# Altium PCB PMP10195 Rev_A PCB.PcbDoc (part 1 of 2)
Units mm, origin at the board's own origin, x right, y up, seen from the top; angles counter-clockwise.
Board outline 60.32 x 50 mm, 4 copper layers (Top Layer, Signal Layer 1, Signal Layer 2, Bottom Layer), stack 2.028 mm thick; 90 components, 50 nets, 184 pads, 78 vias.
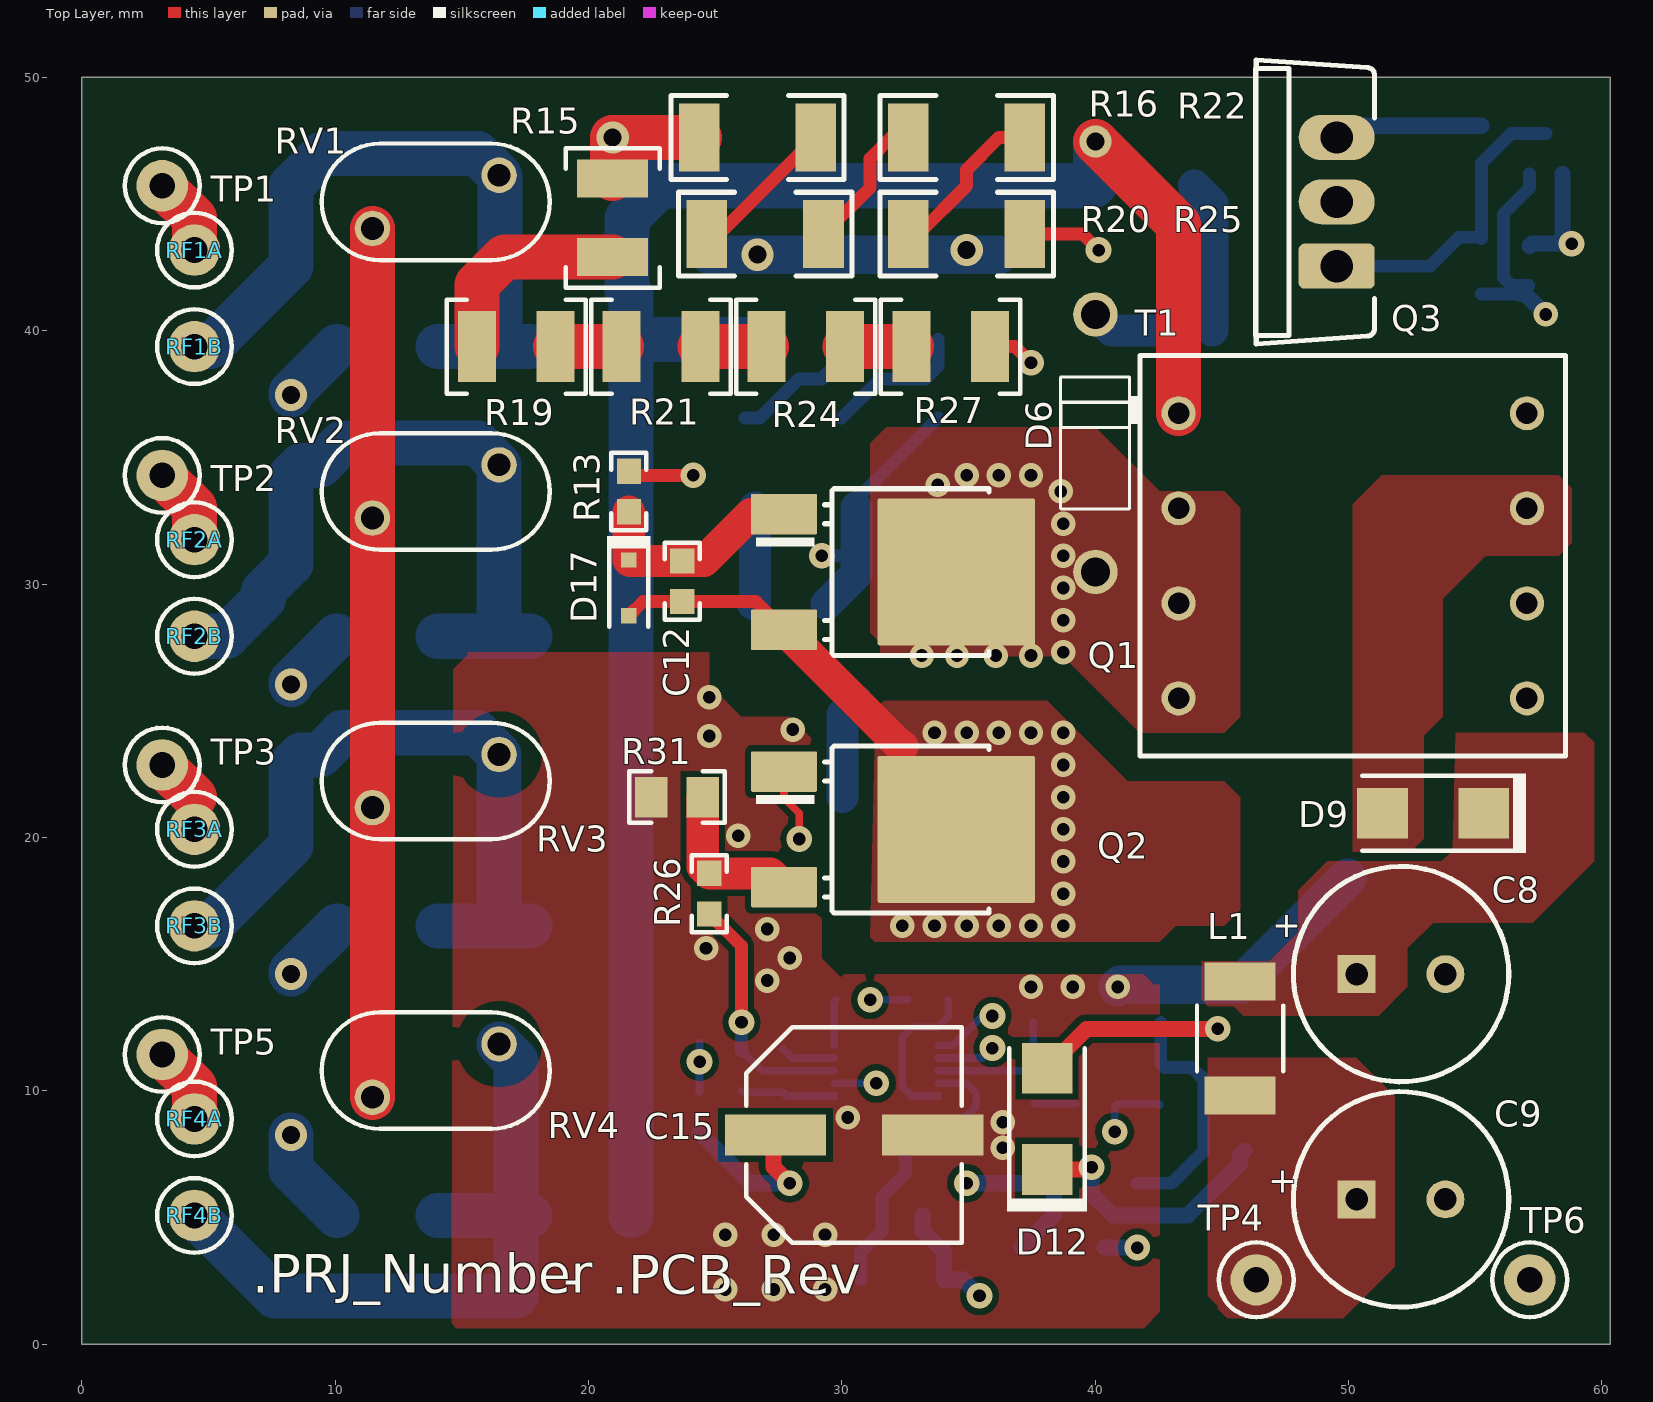
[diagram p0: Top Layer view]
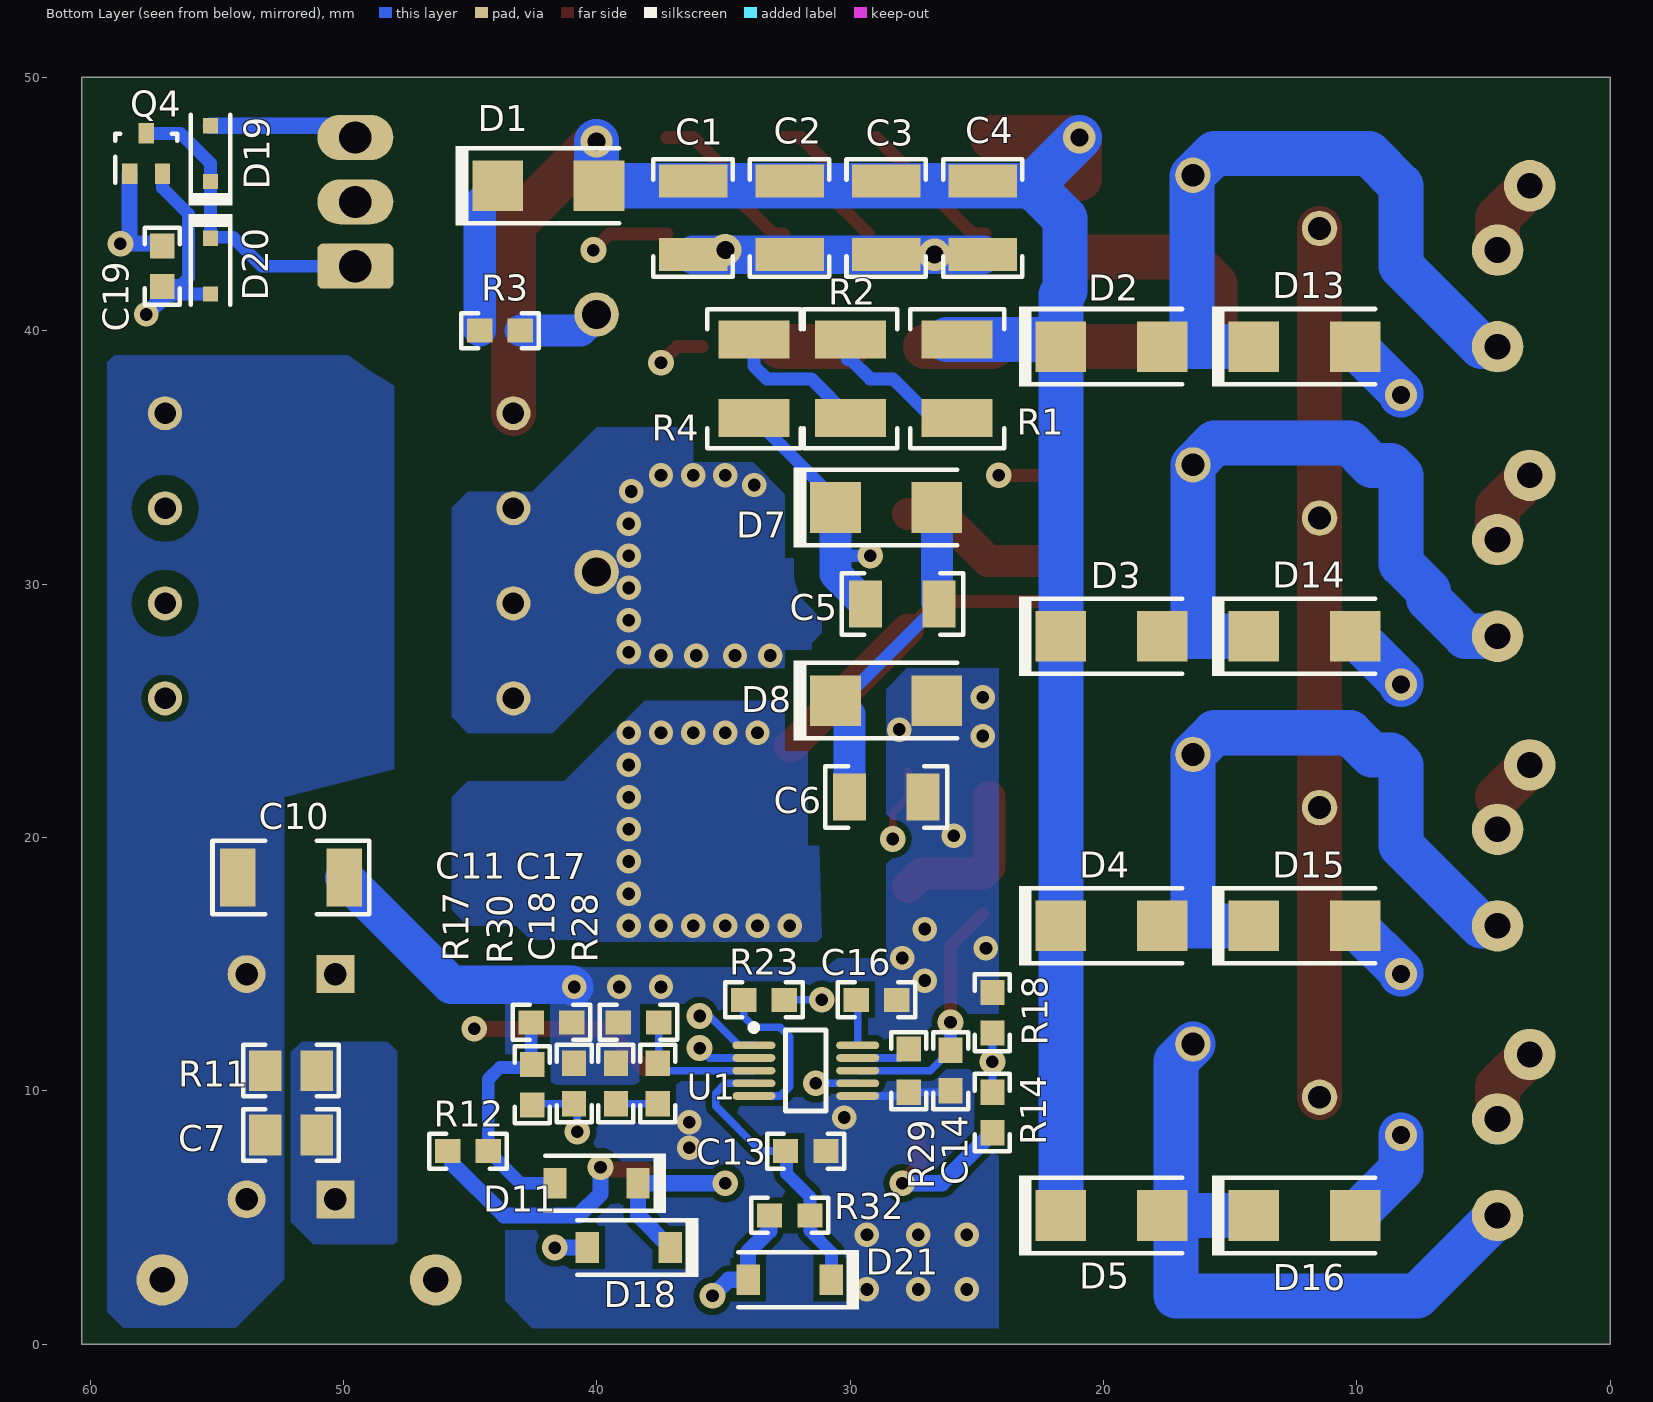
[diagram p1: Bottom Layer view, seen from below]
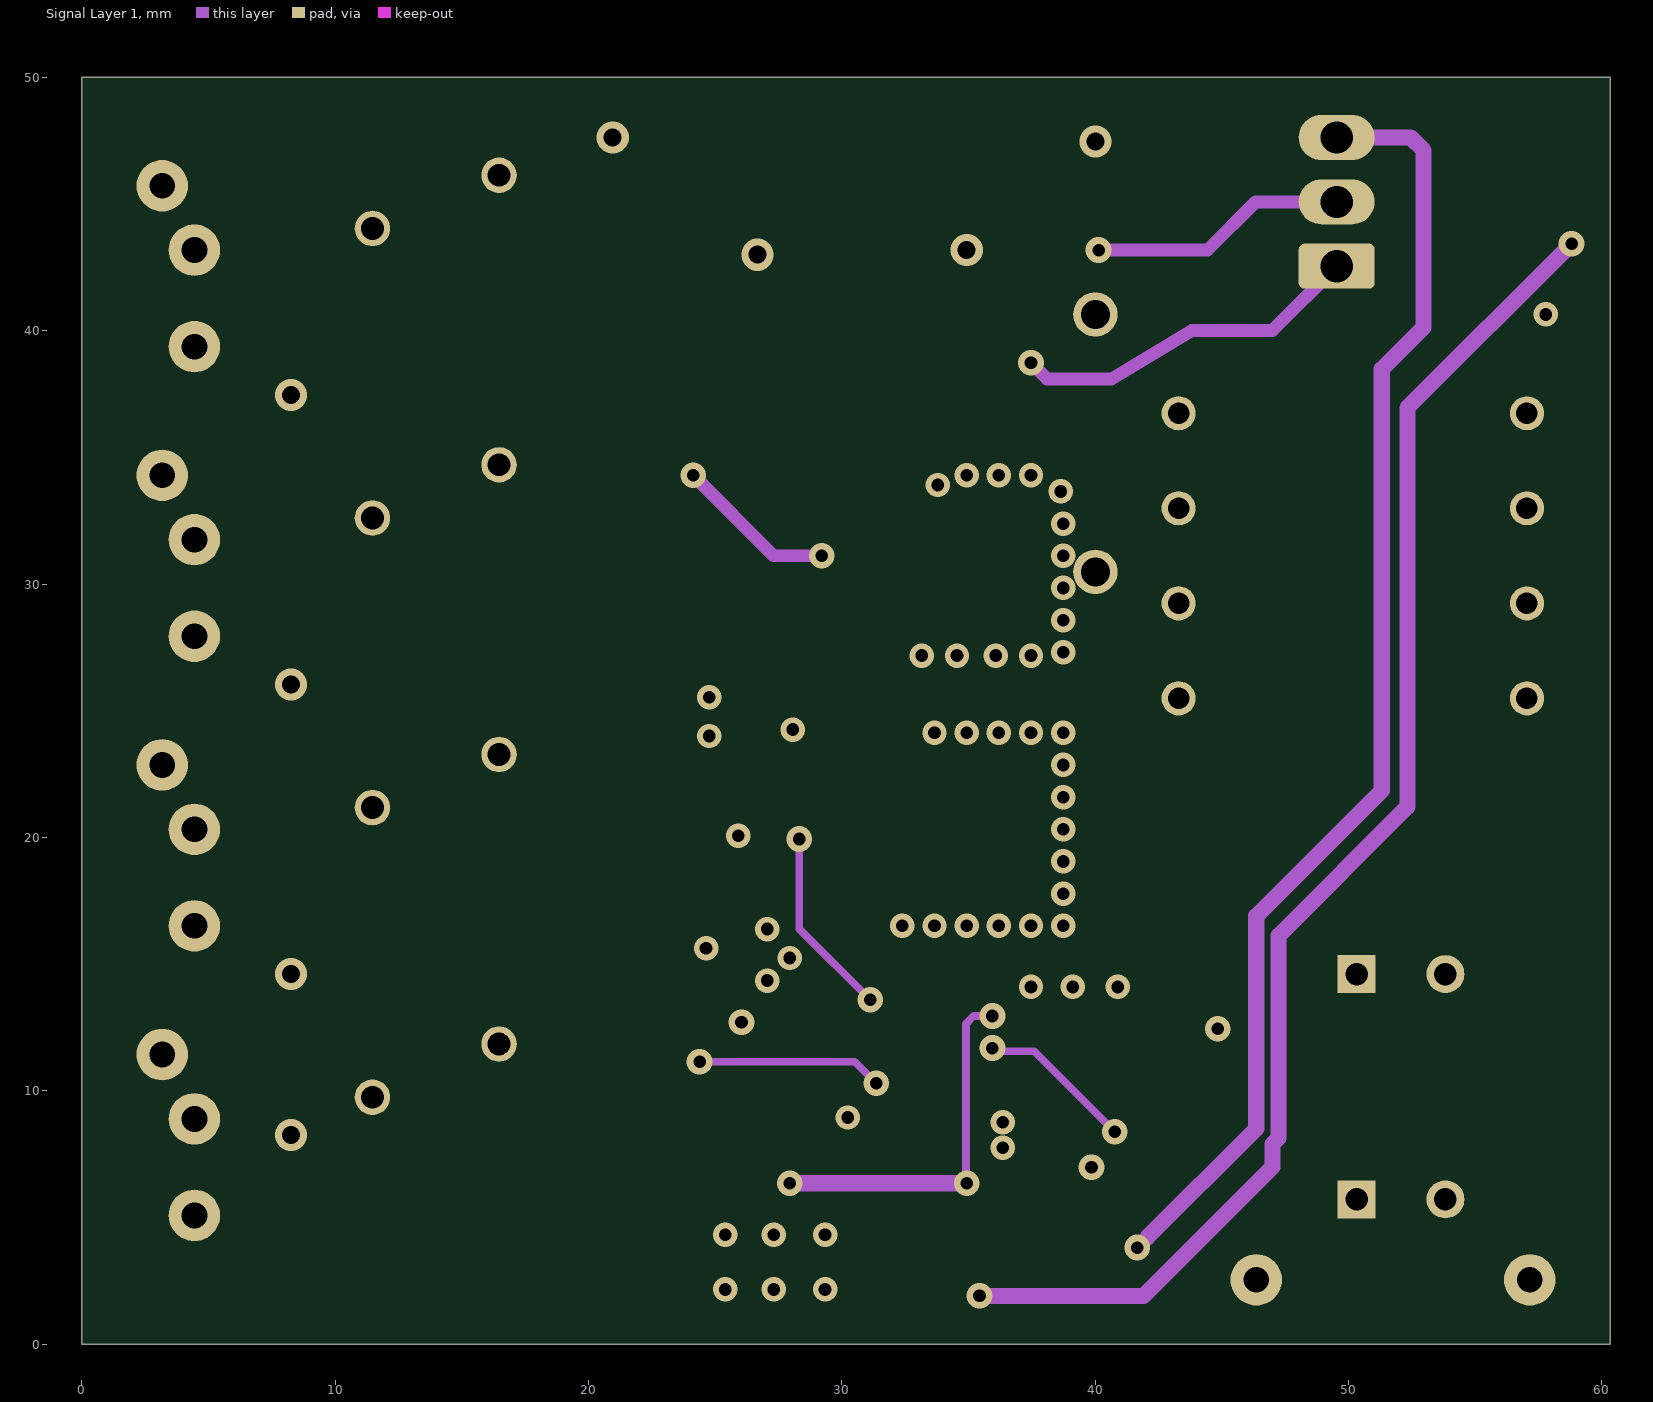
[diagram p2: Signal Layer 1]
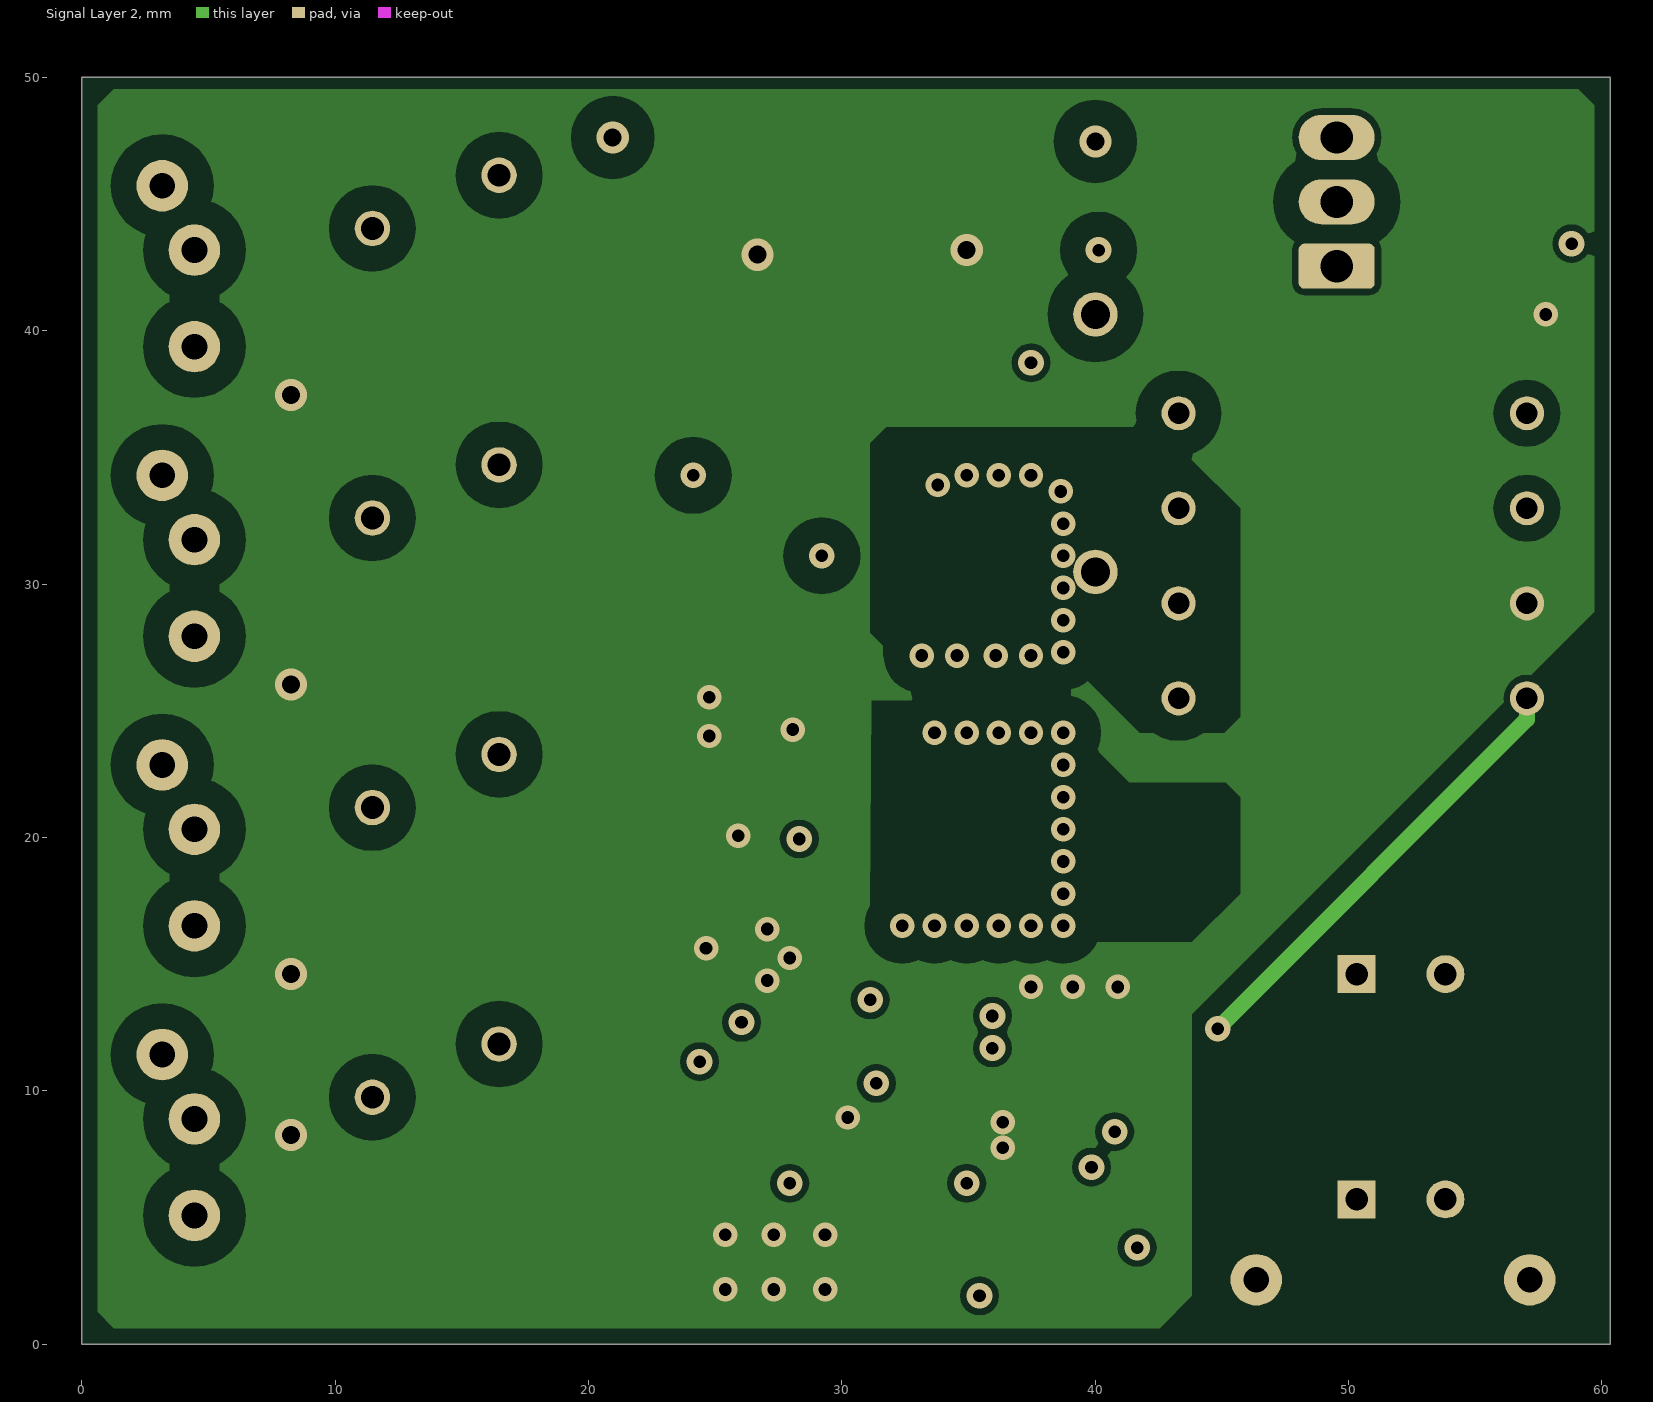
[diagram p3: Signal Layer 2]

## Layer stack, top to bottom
Top Solder: solder mask 0.0102, Solder Resist, Dk 3.5
Top Layer: signal copper 0.0356
Dielectric1: core 1.5037, FR-4, Dk 4.8
Signal Layer 1: signal copper 0.036
Dielectric 2: prepreg 0.127, Dk 4.2
Signal Layer 2: signal copper 0.036
Dielectric 3: core 0.254, Dk 4.2
Bottom Layer: signal copper 0.0356
Bottom Solder: solder mask 0.0102, Solder Resist, Dk 3.5

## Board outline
0,0 0,50 60.325,50 60.325,0

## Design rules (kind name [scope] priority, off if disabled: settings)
AcuteAngle [All] p1: minimum=4.50000000000000E+0001 checktracksonly=FALSE
AssemblyTestPointUsage [All] p1: valid=2
Clearance "Schematic Clearance Constraint_36" [InNet('NetQ3_2')] p1: gap=1
Clearance "Schematic Clearance Constraint_12" [InNet('NetC18_1')] p2: gap=0.25
Clearance "Schematic Clearance Constraint_35" [InNet('NetRF2A_1')] p3: gap=1
Clearance "Schematic Clearance Constraint_22" [InNet('NetRF3A_1')] p4: gap=1
Clearance "Schematic Clearance Constraint_21" [InNet('NetRF4A_1')] p5: gap=1
Clearance "Schematic Clearance Constraint_20" [InNet('NetC7_1')] p6: gap=0.25
Clearance "Schematic Clearance Constraint_19" [InNet('NetC8_1')] p7: gap=0.25
Clearance "Schematic Clearance Constraint_18" [InNet('NetC11_1')] p8: gap=0.25
Clearance "Schematic Clearance Constraint_17" [InNet('NetC13_1')] p9: gap=0.25
Clearance "Schematic Clearance Constraint_16" [InNet('NetC14_1')] p10: gap=0.25
Clearance "Schematic Clearance Constraint_15" [InNet('NetC15_1')] p11: gap=0.25
Clearance "Schematic Clearance Constraint_14" [InNet('NetC16_1')] p12: gap=0.25
Clearance "Schematic Clearance Constraint_13" [InNet('NetC17_1')] p13: gap=0.25
Clearance "Schematic Clearance Constraint_11" [InNet('NetC19_1')] p14: gap=0.25
Clearance "Schematic Clearance Constraint_10" [InNet('NetD12_1')] p15: gap=0.25
Clearance "Schematic Clearance Constraint_9" [InNet('NetD12_2')] p16: gap=0.25
Clearance "Schematic Clearance Constraint_8" [InNet('NetD18_2')] p17: gap=0.25
Clearance "Schematic Clearance Constraint_7" [InNet('NetD19_1')] p18: gap=0.25
Clearance "Schematic Clearance Constraint_6" [InNet('NetQ2_1')] p19: gap=0.25
Clearance "Schematic Clearance Constraint_5" [InNet('NetQ2_3')] p20: gap=0.25
Clearance "Schematic Clearance Constraint_4" [InNet('NetR14_1')] p21: gap=0.25
Clearance "Schematic Clearance Constraint_1" [InNet('NetR29_2')] p22: gap=0.25
Clearance "Schematic Clearance Constraint_34" [InNet('NetC12_2')] p23: gap=1
Clearance "Schematic Clearance Constraint_33" [InNet('NetC12_1')] p24: gap=1
Clearance "Schematic Clearance Constraint_32" [InNet('NetD4_2')] p25: gap=1
Clearance "Schematic Clearance Constraint_31" [InNet('NetC5_1')] p26: gap=1
Clearance "Schematic Clearance Constraint_30" [InNet('NetD3_2')] p27: gap=1
Clearance "Schematic Clearance Constraint_29" [InNet('NetRV1_2')] p28: gap=1
Clearance "Schematic Clearance Constraint_28" [InNet('NetD1_1')] p29: gap=1
Clearance "Schematic Clearance Constraint_27" [InNet('NetD2_2')] p30: gap=1
Clearance "Schematic Clearance Constraint_26" [InNet('NetD5_2')] p31: gap=1
Clearance "Schematic Clearance Constraint_25" [InNet('NetD6_1')] p32: gap=1
Clearance "Schematic Clearance Constraint_24" [InNet('NetD6_2')] p33: gap=1
Clearance "Schematic Clearance Constraint_23" [InNet('NetRF1A_1')] p34: gap=1
Clearance "Schematic Clearance Constraint_3" [InNet('NetR17_1')] p35: gap=0.25
Clearance "Schematic Clearance Constraint_2" [InNet('NetR23_1')] p36: gap=0.25
Clearance "Schematic Clearance Constraint" [InNet('NetC1_1')] p37: gap=1
Clearance Clearance_Keepouts [((IsTrack Or IsArc) And Not InPoly) And IsFree and IsKeepOut vs ((IsTrack Or IsArc) And Not InPoly) And IsFree and IsKeepOut] p38: gap=0
Clearance Clearance_BoardEdge_MountingHoles [OnCopper and InComponentClass('Mounting Holes') vs IsKeepOut] p39: gap=1.016
Clearance Clearance_BoardEdge_Poly [OnCopper and InPoly vs IsKeepOut] p40: gap=0.635
Clearance Clearance_BoardEdge [OnCopper and Not InComponentClass('Logo') and not InComponentClass('FiducialMark') and not InRegion(1000,500,4000,800) and Not IsKeepout vs IsKeepOut] p41: gap=1.905
Clearance Clearance_Poly [InPolygon] p42: gap=0.635
Clearance [All] p43: gap=0.152
ComponentClearance ComponentClearance_MountingHoles_FiducialMarks [InComponentClass('Mounting Holes') vs InComponentClass('FiducialMark')] p1: gap=1.27 collisioncheckmode=3 verticalgap=0.254 showdistances=FALSE
ComponentClearance ComponentClearance_Shunt [InComponentClass('Header') vs InComponentClass('Shunt')] p2: gap=0 collisioncheckmode=3 verticalgap=0 showdistances=FALSE
ComponentClearance ComponentClearance_Logo [InComponentClass('Logo')] p3: gap=1.27 collisioncheckmode=3 verticalgap=0.254 showdistances=FALSE
ComponentClearance ComponentClearance_ScrewToNut [(HasFootprint('NY PMS 440 0025 PH')) vs (HasFootprint('Keystone_1902C'))] p4: gap=0.127 collisioncheckmode=3 verticalgap=0.254 showdistances=FALSE
ComponentClearance ComponentClearance_MountingHoles [InComponentClass('Mounting Holes')] p5: gap=6.35 collisioncheckmode=3 verticalgap=2540 showdistances=FALSE
ComponentClearance ComponentClearance_SmallPassives [HasFootprint('0201*') or HasFootprint('0402*') or HasFootprint('0508') or HasFootprint('0603*') or HasFootprint('0612') or HasFootprint('0805*') or HasFootprint('0815*') or HasFootprint('0830*') or HasFootprint('1206*') or HasFootprint('1210*') or HasFootprint('1808*') or HasFootprint('1812*') or HasFootprint('1825*') or HasFootprint('2010*') or HasFootprint('2220*') or HasFootprint('2225*') or HasFootprint('2512*') or HasFootprint('2728*') or HasFootprint('3518*') vs HasFootprint('0201*') or HasFootprint('0402*') or HasFootprint('0508') or HasFootprint('0603*') or HasFootprint('0612') or HasFootprint('0805*') or HasFootprint('0815*') or HasFootprint('0830*') or HasFootprint('1206*') or HasFootprint('1210*') or HasFootprint('1808*') or HasFootprint('1812*') or HasFootprint('1825*') or HasFootprint('2010*') or HasFootprint('2220*') or HasFootprint('2225*') or HasFootprint('2512*') or HasFootprint('2728*') or HasFootprint('3518*')] p6: gap=0.508 collisioncheckmode=3 verticalgap=0.254 showdistances=FALSE
ComponentClearance ComponentClearance_THtoSMT [IsThruComponent vs IsSMTComponent] p7: gap=0.2 collisioncheckmode=3 verticalgap=0.762 showdistances=FALSE
ComponentClearance ComponentClearance_THtoTH [IsThruComponent vs IsThruComponent] p8: gap=0.2 collisioncheckmode=3 verticalgap=0.762 showdistances=FALSE
ComponentClearance [All] p9: gap=0.2 collisioncheckmode=3 verticalgap=0.254 showdistances=FALSE
DiffPairsRouting [All] p1: maxlimit=2.54 minlimit=0.254 mostfreqgap=0.254 toplayer_minwidth=0.381 toplayer_maxwidth=0.381 toplayer_prefwidth=0.381 midlayer1_minwidth=0.381 midlayer1_maxwidth=0.381 midlayer1_prefwidth=0.381 midlayer2_minwidth=0.381 midlayer2_maxwidth=0.381 midlayer2_prefwidth=0.381 bottomlayer_minwidth=0.381 bottomlayer_maxwidth=0.381 bottomlayer_prefwidth=0.381 maxuncoupledlength=25.4
FabricationTestPointUsage TestPointUsage [All] p1: valid=2 allowmultiple=FALSE
FabricationTestpoint Testpoint [All] p1: side=3 testpointundercomponent=TRUE minsize=1.016 maxsize=2.54 preferedsize=1.524 minholesize=0 maxholesize=1.016 preferedholesize=0.813 testpointgrid=0.025 allowsidetop=TRUE allowsidebottom=TRUE usegrid=TRUE gridtolerance=0
FanoutControl Fanout_LCC [IsLCC] p1: bgadir=Out bgaviamode=Centered fanoutstyle=Auto fanoutdirection=Alternating viagrid=0.025 // Fanout_LCC (Default Rule)
FanoutControl Fanout_BGA [IsBGA] p2: bgadir=Out bgaviamode=Centered fanoutstyle=Auto fanoutdirection=Alternating viagrid=0.025 // Fanout_BGA (Default Rule)
FanoutControl Fanout_Default [All] p4: bgadir=Out bgaviamode=Centered fanoutstyle=Auto fanoutdirection=Alternating viagrid=0.025 // Fanout_Default (Default Rule)
FanoutControl Fanout_Small [(CompPinCount < 5)] p5: bgadir=Out bgaviamode=Centered fanoutstyle=Auto fanoutdirection=OutThenIn viagrid=0.025 // Fanout_Small (Default Rule)
HoleSize [All] p1: absolutevalues=TRUE maxlimit=6.375 minlimit=0.3 maxpercent=80.000 minpercent=20.000
MinimumAnnularRing MinimumAnnularRing_ThermalPadVias [IsVia and InAnyComponent] p1: minimumring=0.15
MinimumAnnularRing [All] p2: minimumring=0.15
MinimumSolderMaskSliver MinimumSolderMaskSliver_Logo [InComponentClass('Logo') vs InComponentClass('Logo')] p1: minsoldermaskwidth=0.018
MinimumSolderMaskSliver [All] p2: minsoldermaskwidth=0.1
PlaneConnect [All] p1: planeconnectstyle=Relief reliefexpansion=0.254 reliefentries=4 reliefconductorwidth=0.254 reliefairgap=0.254
PolygonConnect PolygonConnect_15 [All vs IsNamedPolygon('Cooling C12_2 Bottom')] p1: connectstyle=Direct reliefconductorwidth=0.254 reliefentries=4 polygonreliefangle="90 Angle" airgapwidth=0.254
PolygonConnect PolygonConnect_14 [All vs IsNamedPolygon('Cooling C12_2 Bottom')] p2: connectstyle=Direct reliefconductorwidth=0.254 reliefentries=4 polygonreliefangle="90 Angle" airgapwidth=0.254
PolygonConnect PolygonConnect_13 [All vs IsNamedPolygon('Cooling D6_2 Bottom')] p3: connectstyle=Direct reliefconductorwidth=0.254 reliefentries=4 polygonreliefangle="90 Angle" airgapwidth=0.254
PolygonConnect PolygonConnect_12 [All vs IsNamedPolygon('Signal Layer 1-No Net')] p4: connectstyle=Direct reliefconductorwidth=0.254 reliefentries=4 polygonreliefangle="90 Angle" airgapwidth=0.254
PolygonConnect PolygonConnect_11 [All vs IsNamedPolygon('Top Layer-No Net 6')] p5: connectstyle=Direct reliefconductorwidth=0.254 reliefentries=4 polygonreliefangle="90 Angle" airgapwidth=0.254
PolygonConnect PolygonConnect_10 [All vs IsNamedPolygon('Bottom Layer-No Net 2')] p6: connectstyle=Direct reliefconductorwidth=0.254 reliefentries=4 polygonreliefangle="90 Angle" airgapwidth=0.254
PolygonConnect PolygonConnect_9 [All vs IsNamedPolygon('Top Layer-No Net 5')] p7: connectstyle=Direct reliefconductorwidth=0.254 reliefentries=4 polygonreliefangle="90 Angle" airgapwidth=0.254
PolygonConnect PolygonConnect_8 [All vs IsNamedPolygon('Bottom Layer-No Net 1')] p8: connectstyle=Direct reliefconductorwidth=0.254 reliefentries=4 polygonreliefangle="90 Angle" airgapwidth=0.254
PolygonConnect PolygonConnect_7 [All vs IsNamedPolygon('Bottom Layer-No Net 1')] p9: connectstyle=Direct reliefconductorwidth=0.254 reliefentries=4 polygonreliefangle="90 Angle" airgapwidth=0.254
PolygonConnect PolygonConnect_6 [All vs IsNamedPolygon('Bottom Layer-No Net')] p10: connectstyle=Direct reliefconductorwidth=0.254 reliefentries=4 polygonreliefangle="90 Angle" airgapwidth=0.254
PolygonConnect PolygonConnect_5 [All vs IsNamedPolygon('Top Layer-No Net 4')] p11: connectstyle=Direct reliefconductorwidth=0.254 reliefentries=4 polygonreliefangle="90 Angle" airgapwidth=0.254
PolygonConnect PolygonConnect_4 [All vs IsNamedPolygon('Top Layer-No Net 3')] p12: connectstyle=Direct reliefconductorwidth=0.254 reliefentries=4 polygonreliefangle="90 Angle" airgapwidth=0.254
PolygonConnect PolygonConnect_3 [All vs IsNamedPolygon('Top Layer-No Net 2')] p13: connectstyle=Direct reliefconductorwidth=0.254 reliefentries=4 polygonreliefangle="90 Angle" airgapwidth=0.254
PolygonConnect PolygonConnect_2 [All vs IsNamedPolygon('Top Layer-No Net 1')] p14: connectstyle=Direct reliefconductorwidth=0.254 reliefentries=4 polygonreliefangle="90 Angle" airgapwidth=0.254
PolygonConnect PolygonConnect_1 [All vs IsNamedPolygon('Top Layer-No Net')] p15: connectstyle=Direct reliefconductorwidth=0.254 reliefentries=4 polygonreliefangle="90 Angle" airgapwidth=0.254
PolygonConnect [All] p16: connectstyle=Relief reliefconductorwidth=0.254 reliefentries=4 polygonreliefangle="90 Angle" airgapwidth=0.254
RoutingVias ThermalPadVias [IsVia and InAnyComponent] p1: holewidth=0.5 width=1.2 viastyle="Through Hole" minholewidth=0.3 minwidth=0.6 maxholewidth=0.8 maxwidth=2
RoutingVias [All] p2: holewidth=0.406 width=0.864 viastyle="Through Hole" minholewidth=0.3 minwidth=0.66 maxholewidth=1.016 maxwidth=1.651
SilkToBoardRegionClearance [Not ((IsComment or IsDesignator) And (Hide <> 'False')) and not InRegion(1000,500,4000,800)] p1:
SilkToSilkClearance SilkToSilkClearance_Pb-FreeLogo [(HasFootprint('Pb-Free_Overlay_Medium') OR HasFootprint('Pb-Free_Overlay_Small')) vs (HasFootprint('Pb-Free_Overlay_Medium') OR HasFootprint('Pb-Free_Overlay_Small'))] p1: silktosilkclearance=0
SilkToSilkClearance [All] p2: silktosilkclearance=0.102
SilkToSolderMaskClearance SilkToComonentPadClearance [IsPad and InAnycomponent] p1: minsilkscreentomaskgap=0.127 clearancetoexposedcopper=TRUE
SilkToSolderMaskClearance "Silk to Solder Mask Opening" [All] p2: minsilkscreentomaskgap=0.102 clearancetoexposedcopper=FALSE
SolderMaskExpansion [All] p1: expansion=0.05
UnpouredPolygon [All] p1: allowunpoured=FALSE
Width [All] p1: maxlimit=2.54 minlimit=0.254 preferedwidth=1.27 checkconnectedcopper=TRUE
14 further rules are at their usual default settings.

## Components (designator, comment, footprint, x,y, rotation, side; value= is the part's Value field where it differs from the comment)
C1 "C1210C223KFRACTU" 1210 36.195,44.45 r270 bottom
C2 "C1210C223KFRACTU" 1210 32.385,44.45 r270 bottom
C3 "C1210C223KFRACTU" 1210 28.575,44.45 r270 bottom
C4 "C1210C223KFRACTU" 1210 24.765,44.45 r270 bottom
C5 "GRM31A7U3A470JW31D" 1206 27.94,29.21 r180 bottom
C6 "GRM31A7U3A470JW31D" 1206 28.575,21.59 r180 bottom
C7 "C2012X7R1H105K125AB" 0805_HV 52.07,8.255 r0 bottom
C8 "50ZLJ100MT78X11.5" ZLJ_800X1150 52.07,14.605 r0 top
C9 "50ZLJ100MT78X11.5" ZLJ_800X1150 52.07,5.715 r0 top
C10 "GA342DR7GF102KW02L" 1808 52.07,18.415 r180 bottom
C11 "C1608X7R1E104K" 0603#1 41.783,12.7 r180 bottom
C12 "C1608C0G1H101J" 0603#1 23.7,30.11 r270 top
C13 "C0603C334K4RACTU" 0603#1 31.75,7.62 r180 bottom
C14 "C1608C0G1H561J" 0603#1 26.035,10.795 r270 bottom
C15 "EEE-FC1H220P" SM_RADIAL_E 30.48,8.255 r0 top
C16 "C1608X7R1H103K" 0603#1 28.956,13.589 r180 bottom
C17 "C1608X7R1H222K" 0603#1 38.354,12.7 r0 bottom
C18 "C1608X7R1E104K" 0603#1 39.243,10.287 r90 bottom
C19 "C1608X7R1C224K" 0603#1 57.15,42.545 r270 bottom
D1 "SMAJ110A" SMA 41.91,45.72 r180 bottom
D2 "BYG10Y" SMA 19.685,39.37 r180 bottom
D3 "BYG10Y" SMA 19.685,27.94 r180 bottom
D4 "BYG10Y" SMA 19.685,16.51 r180 bottom
D5 "BYG10Y" SMA 19.685,5.08 r180 bottom
D6 "SF1600" DO-41 40.005,35.56 r270 top
D7 "SMAJ350A" SMA 28.575,33.02 r180 bottom
D8 "SMAJ350A" SMA 28.575,25.4 r180 bottom
D9 "STTH1R06A" SMA 53.34,20.955 r180 top
D11 "BAV21W-7-F" SOD-123 40.005,6.35 r0 bottom
D12 "STTH1R06A" SMA 38.1,8.89 r90 top
D13 "BYG10Y" SMA 12.065,39.37 r180 bottom
D14 "BYG10Y" SMA 12.065,27.94 r180 bottom
D15 "BYG10Y" SMA 12.065,16.51 r180 bottom
D16 "BYG10Y" SMA 12.065,5.08 r180 bottom
D17 "MMSZ5245BS-7-F" sod-323 21.59,29.845 r270 top
D18 "BAV21W-7-F" SOD-123 38.735,3.81 r0 bottom
D19 "MMSZ5245BS-7-F" sod-323 55.245,46.99 r90 bottom
D20 "MMSZ5257BS-7-F" sod-323 55.245,42.545 r270 bottom
D21 "BAV21W-7-F" SOD-123 32.385,2.54 r0 bottom
L1 "NLC453232T-100K-PF" NLC453232T 45.72,12.065 r270 top
Q1 "IPD80R2K8CE" DPAK 31.115,30.48 r0 top
Q2 "IPD80R2K8CE" DPAK 31.115,20.32 r0 top
Q3 "STP3N150" TO-220AB 49.53,45.085 r90 top
Q4 "BSS138W-7-F" SOT-323 57.785,46.99 r90 bottom
R1 "ERJ14NF1004U" 1210M 25.775,38.1 r90 bottom
R2 "ERJ14NF1004U" 1210M 29.98,38.1 r90 bottom
R3 "CRCW0603221RFKEA" 0603#1 43.815,40.005 r0 bottom
R4 "ERJ14NF1004U" 1210M 33.79,38.1 r90 bottom
R11 "CRCW080510K0FKEA" 0805_HV 52.07,10.795 r180 bottom
R12 "CRCW060310R0FKEA" 0603#1 45.085,7.62 r180 bottom
R13 "CRCW060310R0FKEA" 0603#1 21.59,33.655 r270 top
R14 "CRCW0603249KFKEA" 0603#1 24.384,9.144 r270 bottom
R15 "ERJ14NF1004U" 1210M 20.955,44.45 r90 top
R16 "CRCW2010470RJNEF" 2010 26.67,47.625 r180 top
R17 "CRCW060328K0FKEA" 0603#1 42.545,10.238 r90 bottom
R18 "CRCW060322K6FKEA" 0603#1 24.384,13.081 r270 bottom
R19 "ERJ14NF1004U" 1210M 17.145,39.37 r180 top
R20 "CRCW2010470RJNEF" 2010 26.975,43.815 r180 top
R21 "ERJ14NF1004U" 1210M 22.86,39.37 r180 top
R22 "CRCW2010470RJNEF" 2010 34.925,47.625 r180 top
R23 "CRCW060310R0FKEA" 0603#1 33.401,13.589 r180 bottom
R24 "ERJ14NF1004U" 1210M 28.575,39.37 r180 top
R25 "CRCW2010470RJNEF" 2010 34.925,43.815 r180 top
R26 "CRCW06031K00FKEA" 0603#1 24.765,17.78 r270 top
R27 "ERJ14NF1004U" 1210M 34.29,39.37 r180 top
R28 "CRCW06034K75FKEA" 0603#1 37.592,10.287 r90 bottom
R29 "CRCW060363K4FKEA" 0603#2 27.686,10.795 r90 bottom
R30 "CRCW06033K32FKEA" 0603#1 40.894,10.287 r270 bottom
R31 "CRCW08051R00FKEA" 0805_HV 23.495,21.59 r0 top
R32 "CRCW0603475KFKEA" 0603#1 32.385,5.08 r0 bottom
RF1A "5002" Keystone5002 4.445,43.18 r90 top
RF1B "5002" Keystone5002 4.445,39.37 r90 top
RF2A "5002" Keystone5002 4.445,31.75 r90 top
RF2B "5002" Keystone5002 4.445,27.94 r90 top
RF3A "5002" Keystone5002 4.445,20.32 r90 top
RF3B "5002" Keystone5002 4.445,16.51 r90 top
RF4A "5002" Keystone5002 4.445,8.89 r90 top
RF4B "5002" Keystone5002 4.445,5.08 r90 top
RV1 "B72205S0461K101" VAR_S07K300E2 13.97,45.085 r180 top
RV2 "B72205S0461K101" VAR_S07K300E2 13.97,33.655 r180 top
RV3 "B72205S0461K101" VAR_S07K300E2 13.97,22.225 r180 top
RV4 "B72205S0461K101" VAR_S07K300E2 13.97,10.795 r180 top
T1 "EFD15R150-S525" GCI_EFD15R150-S525 50.165,31.115 r0 top
TP1 "5002" Keystone5002 3.175,45.72 r0 top
TP2 "5002" Keystone5002 3.175,34.29 r0 top
TP3 "5002" Keystone5002 3.175,22.86 r0 top
TP4 "5000" Keystone5000 46.355,2.54 r0 top
TP5 "5002" Keystone5002 3.175,11.43 r0 top
TP6 "5001" Keystone5001 57.15,2.54 r0 top
U1 "LM5020MM-2" MUB10A_N 31.75,10.795 r180 bottom

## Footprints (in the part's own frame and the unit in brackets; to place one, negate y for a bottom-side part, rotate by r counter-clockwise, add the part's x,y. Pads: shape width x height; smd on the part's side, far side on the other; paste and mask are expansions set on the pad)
0603#1 [mm] "0603 from SM-752 data"
  rect 1x0.95 smd: 1(-0.8,0) 2(0.8,0)
  silkscreen extent -1.52,-0.69 1.52,0.69, body extent -0.87,-0.47 0.87,0.47, height 1
0603#2 [mm] "0603 from SM-752 data"
  rect 1x0.95 smd: 1(-0.851,0) 2(0.851,0)
  silkscreen extent -1.52,-0.69 1.52,0.69, body extent -0.87,-0.47 0.87,0.47, height 1
0805_HV [mil] "0805 with 30mil clearance between pads"
  rect 50x63 smd: 1(-40,0) 2(40,0)
  silkscreen extent -74,-40 74,40, body extent -43,-29 43,29, height 57
1206 [mm] "1206 from SM-752 data"
  rect 1.3x1.85 smd: 1(-1.45,0) 2(1.45,0)
  silkscreen extent -2.4,-1.21 2.4,1.21, body extent -1.7,-0.9 1.7,0.9, height 1.35
1210 [mm] "1210 from SM-752 data"
  rect 1.3x2.7 smd: 1(-1.45,0) 2(1.45,0)
  silkscreen extent -2.32,-1.57 2.32,1.57, body extent -1.7,-1.35 1.7,1.35, height 1.35
1210M [mm] "1210 from SM-752 data"
  rect 1.5x2.8 smd: 1(-1.55,0) 2(1.55,0)
  silkscreen extent -2.75,-1.85 2.75,1.85, body extent -1.7,-1.35 1.7,1.35, height 1.35
1808 [mm] "Chip Capacitor, Body 4.6x2.0mm, IPC Medium Density"
  rect 1.4x2.3 smd: 1(-2.1,0) 2(2.1,0)
  silkscreen extent -3.1,-1.45 3.1,1.45, body extent -2.47,-1.2 2.47,1.2, height 2.03
2010 [mm] "Chip Capacitor, Body 5.08x2.54mm, IPC Medium Density"
  rect 1.6x2.7 smd: 1(-2.3,0) 2(2.3,0)
  silkscreen extent -3.42,-1.65 3.42,1.65, body extent -2.73,-1.45 2.73,1.45, height 1.66
DO-41 [mm] "diode"
  round 1.75 hole 1.15: 1(-5.08,0) 2(5.08,0)
  silkscreen extent -2.62,-1.37 2.59,1.35, body extent -5.51,-1.36 5.51,1.36, height 2.72
DPAK [mm] "D-PAK, 3-Pads, Body 6.22x6.73mm (max), TO-252AA using nominal STEP model"
  rrect6% 2.6x1.6 smd: 1(-3.4,2.28) 3(-3.4,-2.28)
  rrect2% 6.2x5.8 smd paste-2.9: 4(3.4,0)
  silkscreen extent -4.5,-3.3 4.7,3.28, body extent -3.86,-3.29 5.84,3.29, height 2.48
GCI_EFD15R150-S525 [mm] "TH, 8-Leads, Body 16.8x15.8mm, Pitch 3.75mm"
  round 1.35 hole 0.85: 1(-6.875,5.625) 2(-6.875,1.875) 3(-6.875,-1.875) 4(-6.875,-5.625) 5(6.875,-5.625) 6(6.875,-1.875) 7(6.875,1.875) 8(6.875,5.625)
  silkscreen extent -8.8,-7.9 8.4,7.9, body extent -8.4,-7.9 8.4,7.9, height 8.51
Keystone5000 [mil] "For Keystone 500x miniature loop terminals"
  round 80 hole 40: 1(0,0)
  silkscreen extent -58,-58 58,58, body extent -49,-49 49,49, height 182
Keystone5001 [mil] "For Keystone 500x miniature loop terminals"
  round 80 hole 40: 1(0,0)
  silkscreen extent -58,-58 58,58, body extent -49,-49 49,49, height 182
Keystone5002 [mil] "For Keystone 500x miniature loop terminals"
  round 80 hole 40: 1(0,0)
  silkscreen extent -58,-58 58,58, body extent -49,-49 49,49, height 182
MUB10A_N [mm] "TSSOP, 10-Leads, Body 3x3mm, Pitch 0.5mm, IPC Medium Density"
  oval 1.7x0.3 smd: 1(-2.05,1) 2(-2.05,0.5) 3(-2.05,0) 4(-2.05,-0.5) 5(-2.05,-1) 6(2.05,-1) 7(2.05,-0.5) 8(2.05,0) 9(2.05,0.5) 10(2.05,1)
  silkscreen extent -2.17,-1.6 0.8,1.82, body extent -1.6,-1.6 1.6,1.6, height 1.09
NLC453232T [mm] "TDK"
  rect 1.5x2.8 smd: 1(-2.25,0) 2(2.25,0)
  silkscreen extent -1.3,-1.7 1.3,1.7, body extent -2.4,-1.7 2.4,1.7, height 3.4
SM_RADIAL_E [mm] "8 x 6.2mm:  Panasonic E"
  rect 4x1.6 smd: 1(-3.1,0) 2(3.1,0)
  silkscreen extent -4.25,-4.25 4.25,4.25, body extent -4.26,-4.26 4.26,4.26, height 6.5
SMA [mm] "Molded Diode, 2-Leads, Body 4.3x2.6mm, IPC Medium Density, based on OnSemi component dimensions and land pattern"
  rect 2x2 smd: 1(-2,0) 2(2,0)
  silkscreen extent -3.66,-1.57 2.79,1.57, body extent -2.6,-1.3 2.6,1.3, height 2.42
SOD-123 [mm] "On Semi recommended land pattern"
  rect 0.915x1.22 smd: 1(-1.637,0) 2(1.637,0)
  silkscreen extent -2.74,-1.17 2.03,1.17, body extent -1.93,-0.9 1.93,0.9, height 1.35
sod-323 [mm] "NXP recommended land pattern"
  rect 0.6x0.6 smd paste-0.05: 1(-1.1,0) 2(1.1,0)
  silkscreen extent -2.06,-0.86 1.53,0.86, body extent -1.3,-0.67 1.3,0.68, height 1.1
SOT-323 [mm] "Zetex recommended land pattern.  March 2007"
  rect 0.8x0.6 smd: 1(-0.8,0.65) 2(-0.8,-0.65) 3(0.8,0)
  silkscreen extent -1.14,-1.22 0.77,1.22, body extent -1.13,-1.13 1.12,1.12, height 1.13
TO-220AB [mm] "Copied from Altium's version of TO3B"
  rrect25% 1.778x3 hole 1.27: 1(-2.54,0)
  oval 1.778x3 hole 1.27: 2(0,0) 3(2.54,0)
  silkscreen extent -5.61,-1.49 5.61,3.2, body extent -5.61,-1.49 5.61,3.2, height 19.42
VAR_S07K300E2 [mm] "EPCOS"
  round 1.4 hole 0.9: 1(-2.5,-1.05) 2(2.5,1.05)
  silkscreen extent -4.5,-2.3 4.5,2.3, body extent -4.46,-2.35 4.5,2.35, height 10.99
ZLJ_800X1150 [mm] "Rubycon"
  rect 1.5x1.5 hole 0.889: 1(-1.75,0)
  round 1.5 hole 0.889: 2(1.75,0)
  silkscreen extent -4.25,-4.25 4.25,4.25, body extent -4.22,-4.24 4.24,4.24, height 13.01

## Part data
C1 C2 C3 C4: library part VJ1210Y473KXGAT5Z, "CAP, CERM, 0.022uF, 1500V, +/-10%, X7R, 1210"
C5 C6: "CAP, CERM, 47 pF, 1000 V, +/- 5%, U2J, 1206"
C7: "CAP, CERM, 1 µF, 50 V, +/- 10%, X7R, 0805"
C8 C9: "CAP, AL, 100 µF, 50 V, +/- 20%, 0.12 ohm, TH"
C10: library part VJ1808Y101KXEAT5Z, "CAP, CERM, Safety,1000pF, 250V, +/-10%, X1Y2, 1808"
C11 C18: "CAP, CERM, 0.1 µF, 25 V, +/- 10%, X7R, 0603"
C12: "CAP, CERM, 100 pF, 50 V, +/- 5%, C0G/NP0, 0603"
C13: "CAP, CERM, 0.33uF, 16V, +/-10%, X7R, 0603"
C14: "CAP, CERM, 560 pF, 50 V, +/- 5%, C0G/NP0, 0603"
C15: "CAP, AL, 22 µF, 50 V, +/- 20%, 0.7 ohm, SMD"
C16: "CAP, CERM, 0.01 µF, 50 V, +/- 10%, X7R, 0603"
C17: "CAP, CERM, 2200 pF, 50 V, +/- 10%, X7R, 0603"
C19: "CAP, CERM, 0.22 µF, 16 V, +/- 10%, X7R, 0603"
D1: library part SMAJ120A, "Diode, TVS, Uni, 110V, 400W, SMA"
D2 D3 D4 D5 D13 D14 D15 D16: library part BYG21M-E3/TR, "Diode, Fast Rectifier, 1600 V, 1.5 A, SMA"
D6: library part UF4007-TP, "Diode, Ultrafast, 1600 V, 1 A, TH"
D7 D8: library part SMAJ250A, "Diode, TVS, Uni, 350 V, 400 W, SMA"
D9 D12: "Diode, Ultrafast, 600 V, 1 A, SMA"
D11 D18 D21: "Diode, Switching, 200V, 0.2A, SOD-123"
D17 D19: "Diode, Zener, 15 V, 200 mW, SOD-323"
D20: "Diode, Zener, 33 V, 200 mW, SOD-323"
L1: "Inductor, Wirewound, Ferrite, 10 µH, 0.55 A, 0.5 ohm, SMD"
Q1 Q2: library part IPD30N06S4L-23, "MOSFET, N-CH, 800 V, 6 A, DPAK"
Q3: "MOSFET, N-CH, 1500 V, 2.5 A, TO-220AB"
Q4: "MOSFET, N-CH, 50 V, 0.2 A, SOT-323"
R1 R2 R4 R15 R19 R21 R24 R27: "RES, 1.00 M, 1%, 0.25 W, 1210"
R3: "RES, 221 ohm, 1%, 0.1W, 0603"
R11: "RES, 10.0 k, 1%, 0.125 W, 0805"
R12 R13 R23: "RES, 10.0 ohm, 1%, 0.1W, 0603"
R14: "RES, 249 k, 1%, 0.1 W, 0603"
R16 R20 R22 R25: "RES, 470, 5%, 0.75 W, 2010"
R17: "RES, 28.0 k, 1%, 0.1 W, 0603"
R18: "RES, 22.6 k, 1%, 0.1 W, 0603"
R26: "RES, 1.00k ohm, 1%, 0.1W, 0603"
R28: "RES, 4.75 k, 1%, 0.1 W, 0603"
R29: "RES, 63.4 k, 1%, 0.1 W, 0603"
R30: "RES, 3.32 k, 1%, 0.1 W, 0603"
R31: "RES, 1.00, 1%, 0.125 W, 0805"
R32: "RES, 475 k, 1%, 0.1 W, 0603"
RF1A RF1B RF2A RF2B RF3A RF3B RF4A RF4B TP1 TP2 TP3 TP5: "Test Point, Miniature, White, TH"
RV1 RV2 RV3 RV4: library part B72207S2301K101, "Varistor, 460V, 1.75kA, 7MM Radial, TH"
T1: "Transformer, 2789 uH, TH"
TP4: "Test Point, Miniature, Red, TH"
TP6: "Test Point, Miniature, Black, TH"
U1: "100V Current Mode PWM Controller, 10-pin MSOP"

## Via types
v1: diameter 0.965, hole 0.5, Top Layer to Bottom Layer, 51 vias
v2: diameter 1.016, hole 0.5, Top Layer to Bottom Layer, 19 vias
v3: diameter 1.27, hole 0.711, Top Layer to Bottom Layer, 8 vias

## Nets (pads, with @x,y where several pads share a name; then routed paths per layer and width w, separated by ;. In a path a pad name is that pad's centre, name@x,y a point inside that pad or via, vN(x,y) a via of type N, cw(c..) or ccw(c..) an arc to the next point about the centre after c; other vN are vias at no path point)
GND: C1.2 C2.2 C3.2 C4.2 C6.2 C10.2 C11.2 C13.2 C14.2 C15.2 C16.2 C17.2 C18.2 C19.2 D8.2 D13.2 D14.2 D15.2 D16.2 D20.2 Q4.2 R18.1 R29.1 R30.1 R31.1 T1.6 U1.6 | length 46.9
  Bottom Layer w0.305: C14.2@26.035,9.995 26.086,9.944 R29.1@27.686,9.944 27.835,9.795 U1.6@29.7,9.795
  Bottom Layer w0.508: D20.2@55.245,41.445 56.774,41.445 57.112,41.783 56.425,41.783 56.109,42.099 56.109,44.602 57.135,45.629 Q4.2@57.135,46.19
  Bottom Layer w0.635: C19.2@56.774,41.445 56.98,41.445 v1(57.785,40.64)
  Bottom Layer w1.524: C4.2@24.765,43 C3.2@28.575,43 C2.2@32.385,43 C1.2@36.195,43 ; v1(40.894,14.097) 40.984,14.187 45.742,14.187 C10.2@49.97,18.415
  Bottom Layer w1.778: v3(8.255,8.255) 8.255,6.89 D16.2@10.065,5.08 ; v3(8.255,14.605) 8.255,14.7 D15.2@10.065,16.51 ; v3(8.255,26.035) 8.255,26.13 D14.2@10.065,27.94 ; v3(8.255,37.465) 8.255,37.56 D13.2@10.065,39.37
  other v1: 25.4,2.159 27.305,2.159 29.337,2.159 25.4,4.318 27.305,4.318 29.337,4.318 36.35,7.747 36.35,8.763 30.226,8.945 37.465,14.097 39.116,14.097 27.051,14.351 27.94,15.24 24.638,15.621 27.051,16.383 25.908,20.066 24.765,24.003 28.067,24.257 24.765,25.527
  other v3: 26.67,43 34.925,43.18
GND-S: C7.2 C8.2 C9.2 C10.1 R11.1 T1.8 TP6.1
NetC1_1: C1.1 C2.1 C3.1 C4.1 D1.2 D2.1 D3.1 D4.1 D5.1 R1.2 R15.2 R16.2 T1.1 | length 84.5
  Top Layer w1.778: R15.2@20.955,46 v3(20.955,47.625) R16.2@24.37,47.625 ; v3(40.005,47.47) 43.29,44.185 T1.1@43.29,36.74
  Bottom Layer w1.778: v3(20.955,47.625) 20.955,47.62 22.855,45.72 ; D5.1@21.685,5.08 D4.1@21.685,16.51 D3.1@21.685,27.94 D2.1@21.685,39.37 ; R1.2@26.17,39.65 21.965,39.65 D2.1@21.685,39.37 ; v3(40.005,47.47) 40.005,45.815 D1.2@39.91,45.72 22.855,45.72 ; D2.1@21.685,39.37 21.685,41.409 21.526,41.568 21.526,44.432 22.633,45.539 22.674,45.539 22.855,45.72
NetC5_1: C5.1 D7.1 R4.1 R13.1 | length 19.5
  Top Layer w0.508: R13.1@21.59,34.455 21.755,34.29 v2(24.13,34.29)
  Signal Layer 1 w0.508: v2(24.13,34.29) 27.305,31.115 v2(29.21,31.115)
  Bottom Layer w0.508: v2(29.21,31.115) 30.575,31.115 ; D7.1@30.575,33.02 30.575,33.335 R4.1@33.79,36.55
  Bottom Layer w1.27: C5.1@29.39,29.21 30.575,30.395 30.575,31.115 D7.1@30.575,33.02
NetC5_2: C5.2 C6.1 D7.2 D8.1 | length 13.5
  Bottom Layer w0.508: C5.2@26.49,29.21 30.3,25.4 D8.1@30.575,25.4
  Bottom Layer w1.27: C5.2@26.49,29.21 26.575,29.295 D7.2@26.575,33.02 ; C6.1@30.025,21.59 30.025,24.85 D8.1@30.575,25.4
NetC7_1: C7.1 C9.1 L1.2 R11.2 TP4.1
NetC8_1: C8.1 D9.1 L1.1
NetC11_1: C11.1 D11.2 R12.2 R17.2 | length 9.6
  Bottom Layer w0.508: D11.2@41.642,6.35 43.015,6.35 R12.2@44.285,7.62 44.285,10.452 43.815,10.922 42.737,10.922 42.583,11.076 C11.1@42.583,12.7
NetC12_1: C12.1 D17.1 Q1.1 R13.2 | length 8.8
  Top Layer w1.27: R13.2@21.59,32.855 D17.1@21.59,30.945 21.625,30.91 C12.1@23.7,30.91 24.56,30.91 26.41,32.76 Q1.1@27.715,32.76
NetC12_2: C12.2 D17.2 Q1.3 Q2.4 | length 13.4
  Top Layer w0.508: D17.2@21.59,28.745 22.155,29.31 C12.2@23.7,29.31 26.605,29.31 Q1.3@27.715,28.2
  Top Layer w1.27: Q1.3@27.715,28.2 32.315,23.6 32.385,23.6
  other v1: 32.385,16.51 33.655,16.51 34.925,16.51 36.195,16.51 37.465,16.51 38.735,16.51 38.735,17.78 38.735,19.05 38.735,20.32 38.735,21.59 38.735,22.86 33.655,24.13 34.925,24.13 36.195,24.13 37.465,24.13 38.735,24.13
NetC13_1: C13.1 D21.1 R32.1 U1.4 | length 11.5
  Bottom Layer w0.305: C13.1@32.55,7.62 33.528,7.62 35.306,9.398 35.306,9.906 34.917,10.295 U1.4@33.8,10.295
  Bottom Layer w0.508: D21.1@30.748,2.54 30.734,2.554 30.734,3.619 31.585,4.47 R32.1@31.585,5.08 31.585,5.804 32.512,6.731 C13.1@32.512,7.582
NetC14_1: C14.1 R26.2 U1.8 | length 9.9
  Top Layer w0.508: R26.2@24.765,16.98 26.035,15.71 v2(26.035,12.7)
  Bottom Layer w0.305: C14.1@26.035,11.595 26.835,10.795 U1.8@29.7,10.795
  Bottom Layer w0.508: C14.1@26.035,11.595 v2(26.035,12.7)
NetC15_1: C15.1 D11.1 D18.1 R14.2 U1.1 | length 30.2
  Top Layer w0.635: C15.1@27.38,8.255 27.305,8.18 27.305,6.985 v2(27.94,6.35)
  Signal Layer 1 w0.305: v2(34.925,6.35) 34.9,6.375 34.9,12.645 35.209,12.954 v2(35.941,12.954)
  Signal Layer 1 w0.635: v2(27.94,6.35) v2(34.925,6.35)
  Bottom Layer w0.305: U1.1@33.8,11.795 34.401,11.795 35.56,12.954 v2(35.941,12.954)
  Bottom Layer w0.635: R14.2@24.384,8.344 26.378,6.35 v2(27.94,6.35) ; v2(34.925,6.35) D11.1@38.368,6.35 38.368,5.08 D18.1@37.098,3.81
NetC16_1: C16.1 U1.10 | length 1.8
  Bottom Layer w0.305: U1.10@29.7,11.795 29.7,13.533 C16.1@29.756,13.589
NetC17_1: C17.1 R28.2 U1.3 | length 5.5
  Bottom Layer w0.305: U1.3@33.8,10.795 37.3,10.795 R28.2@37.592,11.087 37.554,11.125 C17.1@37.554,12.7
NetC18_1: C18.1 R28.1 | length 1.7
  Bottom Layer w0.305: R28.1@37.592,9.487 C18.1@39.243,9.487
NetC19_1: C19.1 D21.2 Q4.1 R32.2 | length 64.3
  Signal Layer 1 w0.635: v2(35.433,1.905) 41.91,1.905 46.99,6.985 46.99,7.892 47.24,8.142 47.24,16.125 52.324,21.209 52.324,36.957 v2(58.801,43.434) v2@58.801,43.307
  Bottom Layer w0.635: R32.2@33.185,5.08 33.185,4.471 34.036,3.619 34.036,2.554 D21.2@34.022,2.54 34.798,2.54 v2(35.433,1.905) ; C19.1@57.15,43.345 57.239,43.434 v2(58.801,43.434) 58.435,43.8 Q4.1@58.435,46.19
NetD1_1: D1.1 R3.2 | length 6
  Bottom Layer w1.27: D1.1@43.91,45.72 44.615,45.015 R3.2@44.615,40.005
